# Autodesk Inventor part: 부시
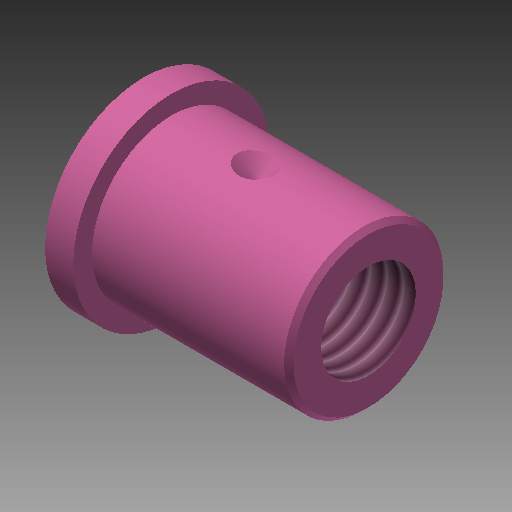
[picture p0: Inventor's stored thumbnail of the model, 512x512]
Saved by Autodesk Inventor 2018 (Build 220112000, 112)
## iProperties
Created: 2019-04
Part Number: 부시
Material: 강철, 연강
Document SubType Name: Modeling
Designer: mduedu
Density: 1 g/cm^3
Appearance: 분홍색
Author: mduedu
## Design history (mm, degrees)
sketch "스케치1"
  geometry: L1 (0, 0)-(3, 0); L2 (3, 0)-(3, 10.5); L3 (3, 10.5)-(0, 10.5); L4 (0, 10.5)-(0, 0); L5 (3, 0)-(24, 0); L6 (24, 0)-(24, 8.5); L7 (24, 8.5)-(3, 8.5); L8 (3, 8.5)-(3, 0)
  constraints: 16 end point, 4 parallel, 2 horizontal, 2 perpendicular
  dimensions: "d0" = 3 distance of L2.end L3.end; "d2" = 24 distance between parallel lines of L6 L4; "d3" = 17 diameter of L7 L5; "d4" = 21 diameter of L3 L1
revolve "회전1" sketch "스케치1" stored, may be unused: angle "d5" = 90 deg
sketch "스케치2"
  geometry: L1 (3, 8.5)-(24, 8.5) reference; L2 (12, 8.5)-(12, 6.5); L3 (12, 6.5)-(14, 8.5); L4 (0, -10.5)-(0, 10.5) reference; 1 further point
  constraints: 4 end point, 2 point on line, 1 perpendicular
  dimensions: "d6" = 12 distance from line of L2.start L4; "d7" = 2 distance of L2.start L3.end; "d8" = 45 deg angle of L3 L2
revolve "회전2" sketch "스케치2" stored, may be unused: angle "d9" = 90 deg
hole "구멍1" diameter "d12" = 10.106; stored, may be unused: countersink angle "d16" = 90 deg, drill point angle "d18" = 118 deg; dims "d10" = 10, "d11" = 10, "d13" = 39, "d14" = 4, "d15" = 2, "d17" = 8
chamfer "모따기1" distance "d19" = 0.5; stored, may be unused: second distance "d20" = 2, angle "d21" = 45 deg
node "작업점1"
  node "작업 평면1"
  node "작업축1"
node "솔리드1"
